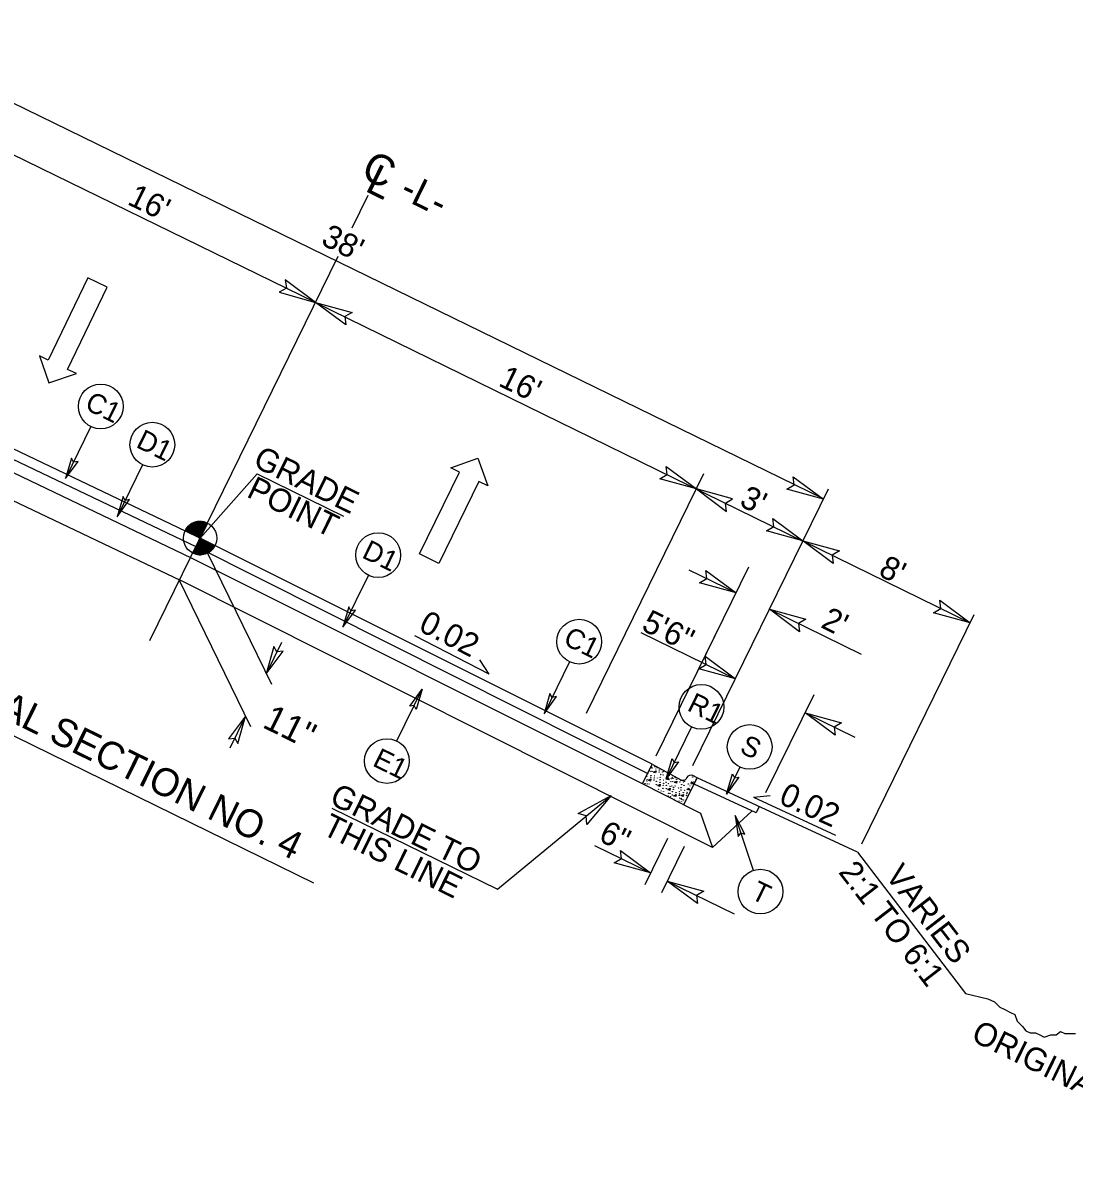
# Model space of a CAD drawing. Extents: x 1518247 to 1523638, y 635234 to 639927.
# Drawn here: x 1522739.6 to 1523190.1, y 636151.1 to 636641.2 of the extents above; entities that cross this region are included whole.
import ezdxf

# ---------------------------------------------------------------- set-up
doc = ezdxf.new("R2010")
doc.units = 0
for name, color, linetype in [('Prop Dimension', 7, 'Continuous'), ('Prop Dimension Text', 7, 'Continuous'), ('Prop Lane Arrow CELL', 7, 'Continuous'), ('Prop Shade Light', 7, 'Continuous'), ('Typical Arrow Superelevation CELL', 7, 'Continuous'), ('Typical Berm CELL', 7, 'Continuous'), ('Typical Berm Information CELL', 7, 'Continuous'), ('Typical Curb CELL', 7, 'Continuous'), ('Typical Grade Point Symbol CELL', 7, 'Continuous'), ('Typical Hinge Slope Arterial CELL', 7, 'Continuous'), ('Typical Hinge Slope Interstate CELL', 7, 'Continuous'), ('Typical ID Circle CELL', 7, 'Continuous'), ('Typical Pavement Slope CELL', 7, 'Continuous'), ('Typical Pavement Slope Information CELL', 7, 'Continuous'), ('Typical Text Centerline CELL', 7, 'Continuous'), ('Typical Text General CELL', 7, 'Continuous'), ('Typical Text Grade Point CELL', 7, 'Continuous'), ('Typical Text ID Circle CELL', 7, 'Continuous'), ('Typical Text Label CELL', 7, 'Continuous')]:
    doc.layers.add(name, color=color, linetype=linetype)

# ---------------------------------------------------------------- blocks, each defined once
blk = doc.blocks.new('TERMINATOR')
at = {"layer": 'Prop Shade Light'}
blk.add_lwpolyline([(-0.469, 0.081), (0, 0), (-0.471, -0.083), (-0.411, 0)], close=True, dxfattribs=at)

msp = doc.modelspace()

# ---------------------------------------------------------------- linework, layer by layer
at = {"layer": 'Prop Dimension'}
for p, q in [((1523082.72, 636437.18), (1522664.78, 636641.22)), ((1522865.04, 636521.4), (1522656.09, 636623.41)), ((1522865.04, 636521.4), (1523073.86, 636419.09)), ((1522839.99, 636447.94), (1522815.54, 636420.37)), ((1522981.07, 636345.3), (1523031.42, 636448.06)), ((1523026.73, 636322.91), (1523084.8, 636441.43)), ((1522815.54, 636420.37), (1522846.13, 636357.79)), ((1523073.89, 636419.17), (1523145.48, 636384.09)), ((1523010.98, 636327.01), (1523050.68, 636408.04)), ((1522806.41, 636402.64), (1522837.22, 636339.62)), ((1523024.92, 636406.81), (1523045.21, 636396.87)), ((1523059.53, 636389.85), (1523098.8, 636370.61)), ((1523099.05, 636289.32), (1523147.24, 636387.67)), ((1523010.98, 636327.02), (1523039.43, 636385.08)), ((1523004.45, 636379.92), (1523044.95, 636360.08)), ((1522850.44, 636375.54), (1522843.9, 636362.19)), ((1523058, 636311.25), (1523078.63, 636353.35)), ((1522834.99, 636344.01), (1522828.28, 636330.32)), ((1523074.77, 636345.47), (1523096.12, 636335.01)), ((1522943.06, 636269.87), (1522991.77, 636310)), ((1522872.06, 636304.66), (1522943.06, 636269.87)), ((1523015.83, 636291.6), (1523006.12, 636271.78)), ((1522984.61, 636288.59), (1523008.59, 636276.84)), ((1523022.99, 636288.09), (1523013.28, 636268.27)), ((1523015.76, 636273.33), (1523044.38, 636259.3))]:
    msp.add_line(p, q, dxfattribs=at)
at = {"layer": 'Prop Lane Arrow CELL'}
for p, q in [((1522767.43, 636531.9), (1522750.46, 636496.7)), ((1522775.73, 636527.9), (1522767.43, 636531.9)), ((1522758.75, 636492.7), (1522775.73, 636527.9)), ((1522750.46, 636496.7), (1522746.69, 636498.52)), ((1522746.69, 636498.52), (1522750.66, 636486.85)), ((1522750.66, 636486.85), (1522762.52, 636490.88)), ((1522762.52, 636490.88), (1522758.75, 636492.7)), ((1522922.99, 636450.48), (1522934.63, 636454.57)), ((1522934.63, 636454.57), (1522938.79, 636442.74)), ((1522909.56, 636413.55), (1522926.75, 636448.64)), ((1522926.75, 636448.64), (1522922.99, 636450.48)), ((1522935.03, 636444.58), (1522917.83, 636409.49)), ((1522938.79, 636442.74), (1522935.03, 636444.58)), ((1522917.83, 636409.49), (1522909.56, 636413.55))]:
    msp.add_line(p, q, dxfattribs=at)
at = {"layer": 'Prop Shade Light'}
for points in [[(1522760.42, 636454.56), (1522757.9, 636445.92), (1522763.24, 636453.24), (1522761.32, 636452.92)], [(1522782.53, 636438.17), (1522780.01, 636429.52), (1522785.34, 636436.85), (1522783.43, 636436.53)], [(1522879.3, 636390.84), (1522876.78, 636382.19), (1522882.12, 636389.52), (1522880.2, 636389.2)], [(1522905.44, 636348.34), (1522910.72, 636355.64), (1522908.21, 636346.93), (1522907.29, 636348.64)], [(1522965.46, 636353.73), (1522962.94, 636345.08), (1522968.27, 636352.41), (1522966.35, 636352.08)], [(1523020.54, 636324.44), (1523015.27, 636317.14), (1523017.78, 636325.85), (1523018.69, 636324.14)], [(1523046.41, 636317.87), (1523041.13, 636310.58), (1523043.64, 636319.29), (1523044.56, 636317.57)], [(1523049.05, 636293.49), (1523044.79, 636301.43), (1523046.12, 636292.46), (1523047.25, 636294.04)]]:
    msp.add_lwpolyline(points, close=True, dxfattribs=at)
at = {"layer": 'Typical Arrow Superelevation CELL'}
msp.add_line((1523052.64, 636309.36), (1523059.91, 636310), dxfattribs=at)
at = {"layer": 'Typical Berm CELL'}
for p, q in [((1523053.82, 636302.62), (1523027.27, 636314.95)), ((1523097.29, 636285.74), (1523028.59, 636317.65))]:
    msp.add_line(p, q, dxfattribs=at)
at = {"layer": 'Typical Berm Information CELL'}
msp.add_line((1523052.64, 636309.36), (1523087.87, 636293), dxfattribs=at)
at = {"layer": 'Typical Curb CELL'}
for p, q in [((1523005.13, 636315.08), (1523009.23, 636323.43)), ((1523009.23, 636323.43), (1523021.51, 636316.77)), ((1523009.89, 636320.06), (1523010.93, 636320.61)), ((1523010.77, 636319.68), (1523009.89, 636320.06)), ((1523010.93, 636320.61), (1523010.77, 636319.68)), ((1523022.86, 636305.95), (1523005.13, 636315.08)), ((1523007.71, 636316.55), (1523008.75, 636317.1)), ((1523008.59, 636316.17), (1523007.71, 636316.55)), ((1523008.75, 636317.1), (1523008.59, 636316.17)), ((1523011.69, 636314.31), (1523012.73, 636314.86)), ((1523012.57, 636313.93), (1523011.69, 636314.31)), ((1523012.73, 636314.86), (1523012.57, 636313.93)), ((1523015.19, 636317.01), (1523016.04, 636317.61)), ((1523016.51, 636316.71), (1523015.19, 636317.01)), ((1523016.04, 636317.61), (1523016.51, 636316.71)), ((1523018.84, 636315.67), (1523019.87, 636316.23)), ((1523019.72, 636315.3), (1523018.84, 636315.67)), ((1523019.87, 636316.23), (1523019.72, 636315.3)), ((1523022.86, 636305.95), (1523028.59, 636317.65)), ((1523024.13, 636317.61), (1523024.17, 636317.69)), ((1523026.06, 636315.93), (1523025.86, 636315.22)), ((1523025.86, 636315.22), (1523027, 636315.07)), ((1523027, 636315.07), (1523026.06, 636315.93)), ((1523028.59, 636317.65), (1523026.73, 636318.56)), ((1523016.01, 636312.6), (1523017.05, 636313.16)), ((1523016.9, 636312.22), (1523016.01, 636312.6)), ((1523017.05, 636313.16), (1523016.9, 636312.22)), ((1523018.53, 636309.91), (1523019.57, 636310.47)), ((1523019.41, 636309.53), (1523018.53, 636309.91)), ((1523019.57, 636310.47), (1523019.41, 636309.53)), ((1523021.67, 636309.96), (1523022.71, 636310.51)), ((1523022.56, 636309.58), (1523021.67, 636309.96)), ((1523022.71, 636310.51), (1523022.56, 636309.58)), ((1523024.13, 636312.63), (1523024.98, 636313.23)), ((1523025.46, 636312.33), (1523024.13, 636312.63)), ((1523024.98, 636313.23), (1523025.46, 636312.33))]:
    msp.add_line(p, q, dxfattribs=at)
for centre in [(1523007.36, 636319.42), (1523008.39, 636320.39), (1523008.48, 636321.61), (1523008.94, 636322.25), (1523009.23, 636321.81), (1523009.24, 636320.38), (1523010.44, 636322.32), (1523010.84, 636321.37), (1523011.52, 636321.94), (1523012.21, 636320.14), (1523012.37, 636320.97), (1523012.97, 636319.01), (1523013.78, 636320.13), (1523014.08, 636320.43), (1523015.82, 636319.33), (1523006.2, 636315.12), (1523007.01, 636316.25), (1523007.05, 636318.29), (1523007.06, 636316.87), (1523007.2, 636314.89), (1523007.99, 636314.94), (1523008.66, 636317.86), (1523008.78, 636318.52), (1523010.03, 636316.63), (1523010.17, 636318.45), (1523010.19, 636317.46), (1523011.03, 636316.05), (1523011.04, 636314.63), (1523011.56, 636317.57), (1523012.64, 636315.62), (1523012.68, 636317.78), (1523012.69, 636316.76), (1523013.97, 636318.77), (1523014.01, 636314.39), (1523014.17, 636315.22), (1523014.17, 636316.59), (1523015.26, 636315.71), (1523015.35, 636314.35), (1523016.3, 636315.04), (1523016.5, 636318.55), (1523017.33, 636316.01), (1523017.43, 636317.23), (1523017.73, 636314.14), (1523017.89, 636317.86), (1523018.17, 636317.42), (1523018.18, 636316), (1523019.24, 636317.63), (1523019.78, 636316.99), (1523021.16, 636315.76), (1523021.31, 636316.59), (1523021.92, 636314.62), (1523022.73, 636315.75), (1523022.92, 636314.39), (1523023.02, 636316.05), (1523024.76, 636314.95), (1523025.45, 636314.16), (1523026.67, 636317.91), (1523027.1, 636315.78), (1523028.11, 636316.9), (1523011.97, 636312.7), (1523013.13, 636311.94), (1523013.94, 636313.06), (1523014.13, 636311.7), (1523015.37, 636312.92), (1523016.09, 636309.82), (1523016.3, 636311), (1523016.9, 636310.95), (1523016.97, 636313.91), (1523017.09, 636309.58), (1523017.87, 636311.66), (1523017.88, 636310.24), (1523018.34, 636312.68), (1523018.49, 636313.51), (1523019.11, 636314.07), (1523019.48, 636311.23), (1523020.51, 636313.19), (1523020.85, 636310), (1523021.01, 636310.82), (1523021.01, 636311.7), (1523021.02, 636310.28), (1523021.62, 636313.4), (1523021.63, 636312.38), (1523022.62, 636311.27), (1523023.12, 636312.21), (1523024, 636310.04), (1523024.15, 636310.87), (1523024.21, 636311.32), (1523018.81, 636308.31), (1523020.84, 636307.7), (1523021.05, 636308.88), (1523021.64, 636308.83), (1523021.84, 636307.46), (1523021.95, 636308.35), (1523022.63, 636308.12)]:
    msp.add_circle(centre, 0.064, dxfattribs=at)
for centre, start, end in [((1523022.42, 636318.45), 241.5117, 333.8962), ((1523025.88, 636316.84), 63.8962, 153.8962)]:
    msp.add_arc(centre, 1.91, start, end, dxfattribs=at)
at = {"layer": 'Typical Grade Point Symbol CELL'}
for p, q in [((1522809.14, 636423.52), (1522815.54, 636420.37)), ((1522815.54, 636420.37), (1522809.14, 636423.52)), ((1522818.68, 636426.78), (1522815.54, 636420.37)), ((1522812.4, 636413.96), (1522815.54, 636420.37)), ((1522815.54, 636420.37), (1522821.95, 636417.23))]:
    msp.add_line(p, q, dxfattribs=at)
for points in [[(1522817.54, 636424.44), (1522812.58, 636426.87)], [(1522817.6, 636424.57), (1522812.76, 636426.94)], [(1522817.66, 636424.7), (1522812.93, 636427.02)], [(1522817.73, 636424.83), (1522813.11, 636427.09)], [(1522817.79, 636424.96), (1522813.3, 636427.15)], [(1522817.85, 636425.08), (1522813.51, 636427.21)], [(1522817.91, 636425.21), (1522813.71, 636427.27)], [(1522817.98, 636425.34), (1522813.93, 636427.32)], [(1522818.04, 636425.47), (1522814.15, 636427.37)], [(1522818.1, 636425.6), (1522814.38, 636427.42)], [(1522818.16, 636425.73), (1522814.63, 636427.46)], [(1522818.23, 636425.85), (1522814.89, 636427.49)], [(1522818.29, 636425.98), (1522815.19, 636427.5)], [(1522818.35, 636426.11), (1522815.49, 636427.51)], [(1522818.42, 636426.24), (1522815.82, 636427.51)], [(1522818.48, 636426.37), (1522816.19, 636427.49)], [(1522818.54, 636426.5), (1522816.63, 636427.43)], [(1522818.6, 636426.62), (1522817.15, 636427.34)], [(1522818.67, 636426.75), (1522817.97, 636427.09)], [(1522815.59, 636420.47), (1522809.18, 636423.61), (1522809.18, 636423.61)], [(1522815.65, 636420.6), (1522809.24, 636423.74)], [(1522815.71, 636420.72), (1522809.32, 636423.86)], [(1522815.78, 636420.85), (1522809.38, 636423.99)], [(1522815.84, 636420.98), (1522809.46, 636424.11)], [(1522815.9, 636421.11), (1522809.54, 636424.23)], [(1522815.97, 636421.24), (1522809.61, 636424.35)], [(1522816.03, 636421.37), (1522809.7, 636424.47)], [(1522816.09, 636421.49), (1522809.78, 636424.59)], [(1522816.15, 636421.62), (1522809.87, 636424.7)], [(1522816.22, 636421.75), (1522809.96, 636424.81)], [(1522816.28, 636421.88), (1522810.05, 636424.93)], [(1522816.34, 636422.01), (1522810.15, 636425.04)], [(1522816.41, 636422.14), (1522810.25, 636425.15)], [(1522816.47, 636422.26), (1522810.34, 636425.27)], [(1522816.53, 636422.39), (1522810.45, 636425.37)], [(1522816.59, 636422.52), (1522810.55, 636425.48)], [(1522816.66, 636422.65), (1522810.66, 636425.59)], [(1522816.72, 636422.78), (1522810.78, 636425.69)], [(1522816.78, 636422.9), (1522810.9, 636425.79)], [(1522816.85, 636423.03), (1522811.02, 636425.89)], [(1522816.91, 636423.16), (1522811.14, 636425.99)], [(1522816.97, 636423.29), (1522811.26, 636426.09)], [(1522817.03, 636423.42), (1522811.39, 636426.18)], [(1522817.1, 636423.55), (1522811.53, 636426.28)], [(1522817.16, 636423.67), (1522811.66, 636426.37)], [(1522817.22, 636423.8), (1522811.81, 636426.45)], [(1522817.29, 636423.93), (1522811.96, 636426.54)], [(1522817.35, 636424.06), (1522812.11, 636426.63)], [(1522817.41, 636424.19), (1522812.25, 636426.71)], [(1522817.47, 636424.31), (1522812.42, 636426.79)], [(1522819.46, 636414.41), (1522813.94, 636417.11)], [(1522819.59, 636414.5), (1522814, 636417.24)], [(1522819.72, 636414.59), (1522814.07, 636417.36)], [(1522819.86, 636414.68), (1522814.13, 636417.49)], [(1522819.98, 636414.78), (1522814.19, 636417.62)], [(1522820.1, 636414.89), (1522814.26, 636417.75)], [(1522820.22, 636414.99), (1522814.32, 636417.88)], [(1522820.34, 636415.09), (1522814.38, 636418)], [(1522820.46, 636415.19), (1522814.44, 636418.13)], [(1522820.56, 636415.29), (1522814.51, 636418.26)], [(1522820.67, 636415.4), (1522814.57, 636418.39)], [(1522820.77, 636415.51), (1522814.63, 636418.52)], [(1522820.86, 636415.62), (1522814.7, 636418.65)], [(1522820.97, 636415.73), (1522814.76, 636418.77)], [(1522821.06, 636415.84), (1522814.82, 636418.9)], [(1522821.15, 636415.96), (1522814.88, 636419.03)], [(1522821.24, 636416.07), (1522814.95, 636419.16)], [(1522821.34, 636416.19), (1522815.01, 636419.29)], [(1522821.41, 636416.31), (1522815.07, 636419.41)], [(1522821.49, 636416.43), (1522815.14, 636419.54)], [(1522821.57, 636416.55), (1522815.2, 636419.67)], [(1522821.64, 636416.67), (1522815.26, 636419.8)], [(1522821.72, 636416.79), (1522815.32, 636419.93)], [(1522821.78, 636416.92), (1522815.39, 636420.06)], [(1522821.86, 636417.04), (1522815.45, 636420.18)], [(1522821.92, 636417.17), (1522821.92, 636417.17), (1522815.51, 636420.31)], [(1522813.35, 636413.58), (1522812.43, 636414.03)], [(1522814.06, 636413.39), (1522812.5, 636414.16)], [(1522814.57, 636413.3), (1522812.56, 636414.29)], [(1522814.99, 636413.26), (1522812.62, 636414.41)], [(1522815.35, 636413.24), (1522812.69, 636414.54)], [(1522815.68, 636413.23), (1522812.75, 636414.67)], [(1522815.97, 636413.25), (1522812.81, 636414.8)], [(1522816.25, 636413.27), (1522812.87, 636414.93)], [(1522816.51, 636413.3), (1522812.94, 636415.05)], [(1522816.76, 636413.34), (1522813, 636415.18)], [(1522816.99, 636413.38), (1522813.06, 636415.31)], [(1522817.21, 636413.44), (1522813.13, 636415.44)], [(1522817.43, 636413.49), (1522813.19, 636415.57)], [(1522817.64, 636413.55), (1522813.25, 636415.7)], [(1522817.83, 636413.61), (1522813.31, 636415.82)], [(1522818.02, 636413.68), (1522813.38, 636415.95)], [(1522818.2, 636413.75), (1522813.44, 636416.08)], [(1522818.37, 636413.82), (1522813.5, 636416.21)], [(1522818.55, 636413.89), (1522813.56, 636416.34)], [(1522818.71, 636413.97), (1522813.63, 636416.47)], [(1522818.86, 636414.06), (1522813.69, 636416.59)], [(1522819.02, 636414.14), (1522813.75, 636416.72)], [(1522819.17, 636414.23), (1522813.82, 636416.85)], [(1522819.32, 636414.31), (1522813.88, 636416.98)]]:
    msp.add_lwpolyline(points, dxfattribs=at)
msp.add_circle((1522815.55, 636420.38), 7.14, dxfattribs=at)
for start, end in [(63.8867, 153.8867), (243.8867, 333.8867)]:
    msp.add_arc((1522815.55, 636420.38), 7.14, start, end, dxfattribs=at)
at = {"layer": 'Typical Hinge Slope Interstate CELL'}
for p, q in [((1523055.11, 636305.33), (1523053.82, 636302.62)), ((1523097.29, 636285.74), (1523143.52, 636225.13))]:
    msp.add_line(p, q, dxfattribs=at)
msp.add_lwpolyline([(1523143.52, 636225.13), (1523153.11, 636222.93), (1523155.9, 636221.56), (1523158.23, 636219.27), (1523160.09, 636218.36), (1523162.88, 636216.99), (1523164.74, 636216.08), (1523165.68, 636213.31), (1523168.02, 636211.02), (1523169.42, 636209.18), (1523171.27, 636208.27), (1523173.59, 636208.29), (1523175.45, 636207.38), (1523177.3, 636206.47), (1523180.07, 636207.41), (1523182.38, 636207.44), (1523184.23, 636208.84), (1523186.08, 636207.93), (1523188.39, 636207.94), (1523190.71, 636207.96)], dxfattribs=at)
at = {"layer": 'Typical ID Circle CELL'}
for p, q in [((1522768.77, 636468.18), (1522757.9, 636445.92)), ((1522790.88, 636451.79), (1522780.01, 636429.52)), ((1522887.65, 636404.46), (1522876.78, 636382.19)), ((1522973.81, 636367.35), (1522962.94, 636345.08)), ((1522899.82, 636333.39), (1522910.72, 636355.64)), ((1523026.17, 636339.39), (1523015.27, 636317.14)), ((1523046.84, 636322.23), (1523041.13, 636310.58)), ((1523052.63, 636277.92), (1523044.79, 636301.43))]:
    msp.add_line(p, q, dxfattribs=at)
for centre in [(1522772.98, 636476.79), (1522795.08, 636460.4), (1522891.86, 636413.07), (1522978.01, 636375.96), (1523030.38, 636348), (1523051.06, 636330.83), (1522895.6, 636324.78), (1523055.66, 636268.83)]:
    msp.add_circle(centre, 9.59, dxfattribs=at)
at = {"layer": 'Typical Pavement Slope CELL'}
for p, q in [((1522576.19, 636512.13), (1522807.3, 636402.21)), ((1522620.26, 636513.67), (1522815.69, 636420.3)), ((1522616.18, 636505.31), (1522811.77, 636411.86)), ((1522618.51, 636509.83), (1522814.01, 636416.68)), ((1523009.23, 636323.43), (1522815.54, 636420.37)), ((1523007.25, 636319.39), (1522813.71, 636416.82)), ((1523005.13, 636315.08), (1522811.28, 636412.1)), ((1523035.06, 636287.7), (1522806.41, 636402.64)), ((1523022.86, 636305.95), (1523030.02, 636302.44)), ((1523030.02, 636302.44), (1523035.06, 636287.7)), ((1523035.06, 636287.7), (1523052.1, 636303.42))]:
    msp.add_line(p, q, dxfattribs=at)
at = {"layer": 'Typical Pavement Slope Information CELL'}
for q in [(1522907.52, 636378.42), (1522935.47, 636368.12)]:
    msp.add_line((1522939.42, 636361.99), q, dxfattribs=at)
at = {"layer": 'Typical Text Centerline CELL'}
for p, q in [((1522880.67, 636553.29), (1522887.54, 636567.31)), ((1522794.05, 636376.51), (1522874.78, 636541.28))]:
    msp.add_line(p, q, dxfattribs=at)
at = {"layer": 'Typical Text Grade Point CELL'}
msp.add_line((1522839.99, 636447.94), (1522876.95, 636429.83), dxfattribs=at)
at = {"layer": 'Typical Text Label CELL'}
msp.add_line((1522682.31, 636361.76), (1522864.21, 636272.63), dxfattribs=at)

# ---------------------------------------------------------------- block references
at = {"layer": 'Prop Dimension'}
for p, xscale, yscale, rotation in [((1522865.04, 636521.4), 33.82820784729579, -36.41552511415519, -26.020730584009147), ((1522865.04, 636521.4), 33.82820784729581, 36.4155251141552, 153.89617982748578), ((1523028.2, 636441.49), 33.82820784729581, 36.4155251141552, -26.103820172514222), ((1523082.64, 636437.03), 33.82820784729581, 36.4155251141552, -26.103820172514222), ((1523028.2, 636441.49), 33.82820784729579, -36.41552511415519, 153.97926941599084), ((1523073.89, 636419.17), 33.82820784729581, 36.4155251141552, -26.103820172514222), ((1523073.89, 636419.17), 33.82820784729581, 36.4155251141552, 153.89617982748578), ((1523045.21, 636396.87), 33.82820784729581, 36.4155251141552, -26.103820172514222), ((1523059.53, 636389.85), 33.82820784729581, 36.4155251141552, 153.89617982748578), ((1523145.48, 636384.09), 33.82820784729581, 36.4155251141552, -26.103820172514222), ((1522843.9, 636362.19), 25.371155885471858, -27.31164383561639, -116.10382017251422), ((1523044.95, 636360.08), 33.82820784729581, 36.4155251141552, -26.103820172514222), ((1522834.99, 636344.01), 25.371155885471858, -27.31164383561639, 63.89617982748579), ((1523074.77, 636345.47), 33.82820784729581, 36.4155251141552, 153.89617982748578), ((1522991.77, 636310), 33.828207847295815, 36.41552511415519, 38.824609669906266), ((1523008.59, 636276.84), 33.82820784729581, 36.4155251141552, -26.103820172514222), ((1523015.76, 636273.33), 33.82820784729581, 36.4155251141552, 153.89617982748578)]:
    msp.add_blockref('TERMINATOR', p, dxfattribs=dict(at, xscale=xscale, yscale=yscale, rotation=rotation))

# ---------------------------------------------------------------- texts
for s, height, rotation, p in [("16'", 9.969, 333.9793, (1522783.91, 636563.66)), ("38'", 9.969, 333.9793, (1522866.88, 636546.41)), ("16'", 9.969, 333.8962, (1522942.93, 636485.9)), ("3'", 9.969, 333.9793, (1523046.16, 636434.4)), ("8'", 9.969, 333.8962, (1523105.75, 636404.49)), ('5\'6"', 9.969, 333.9793, (1523004.18, 636381.13)), ("2'", 9.969, 333.9793, (1523081.05, 636382.28)), ('11"', 11.189, 333.7115, (1522841.8, 636339.46)), ('6"', 9.969, 333.8962, (1522985.82, 636290.81))]:
    msp.add_text(s, height=height, rotation=rotation, dxfattribs=at).set_placement(p)
at = {"layer": 'Prop Dimension Text'}
for s, height, rotation, p in [('-L-', 11.962, 333.9793, (1522900.47, 636566.54)), ('TYPICAL SECTION NO. 4', 11.9625, 333.8962, (1522686.27, 636365.1))]:
    msp.add_text(s, height=height, rotation=rotation, dxfattribs=at).set_placement(p)
at = {"layer": 'Typical Berm Information CELL'}
msp.add_text('0.02', height=9.969, rotation=335.7046, dxfattribs=at).set_placement((1523063.05, 636306.85))
at = {"layer": 'Typical Hinge Slope Arterial CELL'}
for s, height, rotation, p in [('2:1 TO 6:1', 9.969, 307.6683, (1523088.79, 636277.11)), ('VARIES', 9.969, 307.6683, (1523108.8, 636275.67)), ('ORIGINAL GROUND', 9.9687, 333.8962, (1523145.43, 636205.21))]:
    msp.add_text(s, height=height, rotation=rotation, dxfattribs=at).set_placement(p)
at = {"layer": 'Typical Pavement Slope Information CELL'}
msp.add_text('0.02', height=9.969, rotation=332.7504, dxfattribs=at).set_placement((1522908.68, 636380.91))
at = {"layer": 'Typical Text Centerline CELL'}
for s, height, rotation, p in [('C', 13.08, 333.8962, (1522883.81, 636575.27)), ('L', 13.09, 333.8431, (1522885.75, 636569.35))]:
    msp.add_text(s, height=height, rotation=rotation, dxfattribs=at).set_placement(p)
at = {"layer": 'Typical Text General CELL'}
for s, p in [('GRADE TO', (1522870.46, 636306.73)), ('THIS LINE', (1522867.31, 636293.72))]:
    msp.add_text(s, height=9.969, rotation=333.8962, dxfattribs=at).set_placement(p)
at = {"layer": 'Typical Text Grade Point CELL'}
for s, p in [('GRADE', (1522837.71, 636451.35)), ('POINT', (1522835.02, 636438.3))]:
    msp.add_text(s, height=9.969, rotation=333.8962, dxfattribs=at).set_placement(p)
at = {"layer": 'Typical Text ID Circle CELL'}
for s, height, rotation, p in [('C1', 8.581, 333.9793, (1522765.65, 636475.86)), ('D1', 8.581, 333.9793, (1522787.64, 636459.53)), ('D1', 8.581, 333.9793, (1522884.42, 636412.19)), ('C1', 8.581, 333.9793, (1522970.68, 636375.03)), ('R1', 8.581, 333.8962, (1523023.83, 636346.7)), ('S', 8.58, 333.9793, (1523046.34, 636328.67)), ('E1', 8.581, 333.8962, (1522889, 636322.97)), ('T', 8.58, 333.8962, (1523051.04, 636266.07))]:
    msp.add_text(s, height=height, rotation=rotation, dxfattribs=at).set_placement(p)

doc.saveas('drawing.dxf')
